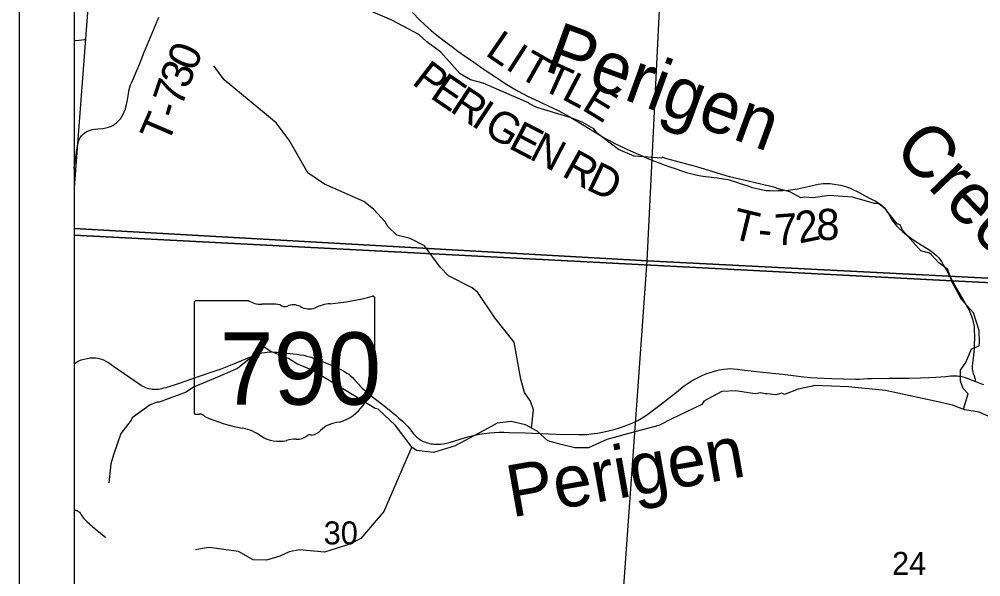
# Model space of a CAD drawing. Extents: x 0 to 34, y 0 to 22.
# Drawn here: x 2 to 3.753, y 18.895 to 19.912 of the extents above; entities that cross this region are included whole.
import ezdxf

# ---------------------------------------------------------------- set-up
doc = ezdxf.new("R2010")
doc.units = 0
for name, color, linetype in [('Default', 7, 'Continuous'), ('GM_X_Minor_River', 7, 'Continuous'), ('GM_X_Minor_River_Text', 7, 'Continuous'), ('GM_X_Section', 7, 'Continuous'), ('GM_X_Section_Text', 7, 'Continuous'), ('GM_X_State_Location', 7, 'Continuous'), ('GM_X_State_Route', 7, 'Continuous'), ('GM_X_State_Shield', 7, 'Continuous'), ('GM_X_Township_Road', 7, 'Continuous'), ('GM_X_Township_Road_Text', 7, 'Continuous'), ('SH_Cut_Line', 7, 'Continuous'), ('SH_Data', 7, 'Continuous')]:
    doc.layers.add(name, color=color, linetype=linetype)

msp = doc.modelspace()

# ---------------------------------------------------------------- linework, layer by layer
at = {"layer": 'Default'}
msp.add_lwpolyline([(6.3694, 20.9), (2.1, 20.9), (2.1, 19.5179), (3.7007, 19.4348), (4.4284, 19.3984), (4.7013, 19.3856), (5.4875, 19.3459)], dxfattribs=at)
for points in [[(2.1, 19.605), (2.1, 19.53), (3.1447, 19.4715), (3.1945, 20.4863), (2.1714, 20.5391)], [(2.1, 19.53), (2.1, 18.4931), (3.0707, 18.4461), (3.1447, 19.4715)], [(2.1, 19.5179), (2.1, 14.1), (5.687, 14.1), (5.785, 14.1504), (5.9145, 14.1963), (5.9273, 14.1959), (5.9341, 14.3014), (6.0001, 15.328), (6.0418, 15.9539), (6.0633, 16.2368), (6.0901, 16.6706), (6.1151, 17.0743), (6.1723, 18.0255), (6.1917, 18.3385), (6.2282, 18.9116), (6.2536, 19.3066), (5.4875, 19.3459), (4.7013, 19.3856), (4.4284, 19.3984), (3.7007, 19.4348)]]:
    msp.add_lwpolyline(points, close=True, dxfattribs=at)
at = {"layer": 'GM_X_Minor_River'}
for points in [[(3.7208, 19.2007), (3.7294, 19.2286), (3.7207, 19.2388), (3.7154, 19.2517), (3.7158, 19.2719), (3.7256, 19.286), (3.7358, 19.3111), (3.7497, 19.3161), (3.7501, 19.3225), (3.7497, 19.3446), (3.7391, 19.3765), (3.7172, 19.4011), (3.6997, 19.4334), (3.6925, 19.4554), (3.6763, 19.4675), (3.663, 19.4823), (3.6592, 19.4854), (3.6433, 19.4895), (3.6097, 19.527), (3.6055, 19.5369), (3.6002, 19.5388), (3.579, 19.5654), (3.5661, 19.5756), (3.5586, 19.576), (3.5189, 19.5873), (3.5011, 19.5884), (3.4765, 19.5906), (3.4471, 19.5863), (3.4316, 19.5874), (3.4248, 19.5859), (3.4043, 19.5969), (3.3813, 19.6033), (3.3775, 19.6052), (3.2947, 19.6247), (3.2353, 19.6428), (3.1801, 19.6571), (3.1718, 19.6605), (3.171, 19.6582), (3.1208, 19.6623), (3.092, 19.6744), (3.0538, 19.7032), (3.047, 19.7119), (3.0262, 19.7244), (3.0058, 19.7323), (2.9434, 19.7508), (2.9298, 19.7576), (2.9283, 19.7595), (2.8746, 19.7822), (2.8454, 19.7954), (2.8227, 19.8015), (2.8035, 19.8121), (2.7683, 19.8519), (2.7429, 19.8704), (2.7285, 19.8841), (2.6794, 19.9102), (2.6453, 19.9249)], [(2.1, 19.8731), (2.1094, 19.8735), (2.1196, 19.875), (2.1188, 19.8746)], [(2.9338, 19.1664), (2.9372, 19.1995), (2.9317, 19.2157), (2.9212, 19.2312), (2.9144, 19.2557), (2.9021, 19.3233), (2.8671, 19.3677), (2.8356, 19.4135), (2.8253, 19.4218), (2.7821, 19.4437), (2.7675, 19.4598), (2.7388, 19.4986), (2.7127, 19.512), (2.688, 19.5181), (2.6718, 19.5338), (2.6668, 19.5427), (2.6459, 19.5658), (2.6282, 19.5796), (2.5566, 19.6112), (2.5262, 19.6315), (2.4921, 19.6914), (2.4685, 19.7226), (2.3734, 19.8012), (2.3581, 19.8218), (2.3549, 19.8268)], [(3.4494, 19.2443), (3.4459, 19.2427), (3.4198, 19.2373), (3.3949, 19.2278), (3.39, 19.23), (3.379, 19.2273), (3.3635, 19.2288), (3.3597, 19.2288), (3.3514, 19.2307), (3.3416, 19.2288), (3.3057, 19.2344), (3.2807, 19.2332), (3.2475, 19.2156), (3.2441, 19.2095), (3.1893, 19.1835), (3.1658, 19.1713), (3.122, 19.1594), (3.071, 19.1456), (3.0374, 19.1303), (3.034, 19.1303), (3.0128, 19.1303), (2.9878, 19.1367), (2.9636, 19.1434), (2.9443, 19.1605), (2.9228, 19.1722), (2.8967, 19.1782), (2.871, 19.1755), (2.8544, 19.166), (2.7943, 19.1339), (2.755, 19.122), (2.724, 19.1257), (2.7164, 19.131), (2.6861, 19.1709), (2.6544, 19.2012), (2.6487, 19.2023), (2.5678, 19.2515), (2.533, 19.2727), (2.5061, 19.2833), (2.4906, 19.2932), (2.4573, 19.3068), (2.4441, 19.3159), (2.4399, 19.3178), (2.4305, 19.3014), (2.4139, 19.2877), (2.398, 19.2751), (2.3572, 19.2575), (2.3179, 19.2411), (2.3043, 19.2319), (2.2552, 19.2139), (2.2514, 19.2135), (2.2385, 19.2089), (2.2061, 19.1853), (2.2042, 19.1807), (2.1849, 19.1567), (2.1717, 19.1175), (2.1668, 19.1012), (2.1631, 19.0666)], [(3.7729, 19.185), (3.7499, 19.1952), (3.7234, 19.1997), (3.7011, 19.2084), (3.6686, 19.2155), (3.579, 19.2347), (3.5113, 19.2417), (3.4494, 19.2443)], [(2.7156, 19.1322), (2.699, 19.0947), (2.6648, 19.0145), (2.6229, 18.9654), (2.6025, 18.9546), (2.5563, 18.9405), (2.5107, 18.9442), (2.4917, 18.9407), (2.4748, 18.9332), (2.4504, 18.9257), (2.4266, 18.9264), (2.3999, 18.9413), (2.346, 18.9487), (2.3343, 18.9468), (2.321, 18.9446)]]:
    msp.add_lwpolyline(points, dxfattribs=at)
at = {"layer": 'GM_X_Section'}
for points in [[(3.1945, 20.4863), (4.2301, 20.4313), (4.1716, 19.4188), (3.1447, 19.4715)], [(3.1447, 19.4715), (4.1716, 19.4188), (4.1036, 18.4009), (3.0707, 18.4461)]]:
    msp.add_lwpolyline(points, close=True, dxfattribs=at)
at = {"layer": 'GM_X_State_Route'}
msp.add_lwpolyline([(2.1, 19.2838), (2.1023, 19.2853), (2.1075, 19.2882), (2.113, 19.2906), (2.1181, 19.2922), (2.1239, 19.2935), (2.129, 19.2943), (2.134, 19.2945), (2.1389, 19.2943), (2.1435, 19.2938), (2.1483, 19.2927), (2.151, 19.2917), (2.1538, 19.2906), (2.1581, 19.2882), (2.1631, 19.2852), (2.1673, 19.2824), (2.1721, 19.2791), (2.2184, 19.2469), (2.2226, 19.2443), (2.2266, 19.242), (2.2304, 19.2404), (2.2333, 19.2392), (2.2365, 19.2383), (2.2398, 19.2377), (2.2427, 19.2373), (2.2457, 19.2372), (2.2488, 19.2372), (2.2512, 19.2374), (2.2536, 19.2376), (2.2569, 19.2381), (2.26, 19.2386), (2.2638, 19.2395), (2.2679, 19.2405), (2.2901, 19.2479), (2.3251, 19.2597), (2.3573, 19.2707), (2.3697, 19.2752), (2.3853, 19.2811), (2.4266, 19.2983), (2.4321, 19.3005), (2.4373, 19.3022), (2.4429, 19.3036), (2.4476, 19.3045), (2.4521, 19.305), (2.4565, 19.3052), (2.4608, 19.3053), (2.4653, 19.3051), (2.4702, 19.3048), (2.5052, 19.3011), (2.512, 19.3002), (2.5185, 19.2991), (2.5241, 19.2977), (2.5297, 19.2961), (2.545, 19.2909), (2.5571, 19.2861), (2.5703, 19.2805), (2.5793, 19.2764), (2.5871, 19.2726), (2.593, 19.2694), (2.5973, 19.2668), (2.6007, 19.2644), (2.6039, 19.2618), (2.6072, 19.2588), (2.6119, 19.2539), (2.6186, 19.2463), (2.6215, 19.2429), (2.6249, 19.2393), (2.6285, 19.236), (2.6326, 19.2324), (2.6368, 19.2291), (2.6414, 19.2255), (2.6621, 19.2095), (2.6776, 19.1971), (2.6815, 19.1939), (2.6862, 19.19), (2.6909, 19.186), (2.695, 19.1823), (2.6987, 19.1789), (2.7022, 19.1754), (2.7057, 19.1719), (2.7087, 19.1685), (2.7114, 19.1654), (2.7157, 19.1601), (2.7183, 19.1568), (2.7213, 19.1534), (2.724, 19.1506), (2.7269, 19.1479), (2.7295, 19.146), (2.7322, 19.1443), (2.7365, 19.1422), (2.7391, 19.1411), (2.7416, 19.1402), (2.7445, 19.1393), (2.7475, 19.1386), (2.7503, 19.1379), (2.7532, 19.1375), (2.7557, 19.1371), (2.7584, 19.137), (2.7609, 19.1369), (2.7634, 19.1369), (2.7679, 19.1371), (2.7726, 19.1375), (2.7769, 19.1383), (2.7815, 19.1393), (2.7921, 19.1424), (2.8056, 19.1467), (2.8174, 19.1502), (2.8296, 19.1533), (2.8386, 19.1552), (2.8477, 19.1567), (2.857, 19.1578), (2.8658, 19.1584), (2.8741, 19.1587), (2.8832, 19.1588), (2.8931, 19.1584), (2.9223, 19.1575), (2.9784, 19.1556), (3.0202, 19.1545), (3.0273, 19.1547), (3.034, 19.155), (3.0433, 19.1557), (3.0538, 19.1571), (3.063, 19.1588), (3.074, 19.1613), (3.0842, 19.164), (3.0961, 19.1676), (3.1091, 19.1721), (3.1183, 19.176), (3.1262, 19.1798), (3.1338, 19.1841), (3.1432, 19.1902), (3.1529, 19.197), (3.1654, 19.2063), (3.1977, 19.232), (3.2053, 19.2381), (3.2103, 19.242), (3.2153, 19.2458), (3.2212, 19.2497), (3.2276, 19.2535), (3.2352, 19.2576), (3.2435, 19.2617), (3.2515, 19.2651), (3.2596, 19.268), (3.2673, 19.2704), (3.2757, 19.2725), (3.2842, 19.274), (3.2909, 19.2747), (3.2952, 19.2748), (3.3013, 19.2747), (3.3093, 19.274), (3.3222, 19.2722), (3.3339, 19.2706), (3.344, 19.2693), (3.3552, 19.2681), (3.3909, 19.2649), (3.4302, 19.2598), (3.4419, 19.2587), (3.4541, 19.2581), (3.4805, 19.2571), (3.5242, 19.2558), (3.5314, 19.2558), (3.5458, 19.2565), (3.5502, 19.2568), (3.5543, 19.257), (3.5857, 19.2575), (3.6216, 19.2576), (3.6428, 19.2578), (3.6579, 19.2584), (3.6704, 19.2591), (3.6886, 19.2606), (3.6976, 19.2616), (3.7025, 19.2619), (3.7062, 19.2618), (3.7095, 19.2616), (3.7128, 19.2613), (3.7157, 19.2609), (3.7197, 19.2599), (3.724, 19.2585), (3.7289, 19.2568), (3.743, 19.2512), (3.7518, 19.2477), (3.7574, 19.2457)], dxfattribs=at)
at = {"layer": 'GM_X_State_Shield'}
for p, q in [((2.6482, 19.2988), (2.6482, 19.4035)), ((2.3186, 19.3951), (2.3186, 19.1949)), ((2.4184, 19.3985), (2.3219, 19.3985)), ((2.6482, 19.2988), (2.6482, 19.2988))]:
    msp.add_line(p, q, dxfattribs=at)
for centre, major_axis, start_param, end_param in [((2.5308, 19.6713), (0.3495, 0), 4.814394, 5.042369), ((2.6445, 19.4039), (0.00367, 0), 6.141152, 7.989035), ((2.3224, 19.3955), (0.00382, 0), 1.712693, 3.28349), ((2.4414, 19.4217), (0.037, 0), 4.042523, 4.731795), ((2.4536, 19.2862), (0.133, 0), 1.404758, 1.657858), ((2.4838, 19.3965), (0.0107, 0), 3.836095, 5.185415), ((2.4995, 19.3734), (0.0222, 0), 0.950623, 2.079405), ((2.5282, 19.4051), (0.0267, 0), 4.081561, 5.145723), ((2.5754, 19.3374), (0.0703, 0), 1.699011, 2.107814), ((2.6474, 19.2911), (0.00568, 0), 1.883978, 3.671073), ((2.6443, 19.2984), (0.00393, 0), 5.05454, 6.418171), ((2.6112, 19.2779), (0.0341, 0), 5.934695, 6.695948), ((2.6613, 19.255), (0.0248, 0), 2.387724, 3.262537), ((2.5504, 19.2417), (0.0874, 0), 5.101752, 6.440018), ((2.3224, 19.1945), (0.00385, 0), 3.00124, 4.508301), ((2.323, 19.215), (0.0294, 0), 4.665946, 4.897461), ((2.329, 19.1834), (0.0106, 0), 0.519207, 1.627899), ((2.4629, 19.3632), (0.2524, 0), 4.195997, 4.488961), ((2.5872, 19.1388), (0.0479, 0), 1.647645, 2.488434), ((2.3876, 19.105), (0.079, 0), 0.823519, 1.323587), ((2.5266, 19.1755), (0.0282, 0), 4.937069, 5.64225), ((2.473, 19.1824), (0.0501, 0), 4.026481, 4.996735), ((2.502, 19.1132), (0.0412, 0), 1.495662, 1.94098), ((2.5056, 19.1674), (0.0267, 0), 4.691044, 5.507374), ((2.5298, 19.148), (0.00752, 0), 1.147584, 2.315152)]:
    msp.add_ellipse(centre, major_axis=major_axis, ratio=0.8, start_param=start_param, end_param=end_param, dxfattribs=at)
at = {"layer": 'GM_X_Township_Road'}
for points in [[(2.1, 19.6399), (2.1008, 19.6452), (2.1037, 19.6648), (2.1056, 19.6773), (2.1069, 19.6845), (2.108, 19.6888), (2.1094, 19.6926), (2.1112, 19.6959), (2.1135, 19.6991), (2.1164, 19.7022), (2.1198, 19.7049), (2.1228, 19.7069), (2.1262, 19.7086), (2.1293, 19.7098), (2.1333, 19.711), (2.1374, 19.7116), (2.1435, 19.7122), (2.1522, 19.7128), (2.1578, 19.7136), (2.1627, 19.7148), (2.1668, 19.7163), (2.1708, 19.7182), (2.1739, 19.7202), (2.1774, 19.7229), (2.1811, 19.7264), (2.1843, 19.7302), (2.1872, 19.7343), (2.1897, 19.7387), (2.1915, 19.7427), (2.1934, 19.748), (2.1946, 19.7521), (2.1957, 19.7566), (2.1966, 19.7611), (2.1989, 19.776), (2.2002, 19.7839), (2.2013, 19.7882), (2.2028, 19.7923), (2.2045, 19.7961), (2.2082, 19.8039), (2.2128, 19.8142), (2.2197, 19.8311), (2.228, 19.8517), (2.2334, 19.8642), (2.2423, 19.8862), (2.2543, 19.9157)], [(2.7166, 19.9238), (2.731, 19.9095), (2.7381, 19.9027), (2.7452, 19.8963), (2.7517, 19.8905), (2.7578, 19.8853), (2.7665, 19.8785), (2.7768, 19.8707), (2.7879, 19.8624), (2.7996, 19.8537), (2.8114, 19.8449), (2.8285, 19.8332), (2.8477, 19.82), (2.8666, 19.8074), (2.8775, 19.8), (2.8857, 19.7947), (2.8945, 19.7892), (2.9054, 19.7828), (2.9162, 19.7768), (2.929, 19.7703), (2.9385, 19.7658), (2.9643, 19.754), (2.9823, 19.7454), (2.9982, 19.7369), (3.0156, 19.7267), (3.0329, 19.7163), (3.0503, 19.7052), (3.0594, 19.6998), (3.0674, 19.6952), (3.0756, 19.6906), (3.0857, 19.6853), (3.0959, 19.6802), (3.1075, 19.6747), (3.1197, 19.6692), (3.1324, 19.6637), (3.146, 19.6581), (3.1563, 19.6537), (3.1666, 19.6497), (3.1754, 19.6465), (3.1859, 19.6428), (3.1955, 19.6395), (3.2053, 19.6361), (3.2159, 19.6326), (3.2237, 19.6304), (3.2334, 19.6282), (3.2425, 19.6265), (3.2511, 19.6252), (3.2615, 19.6239), (3.2719, 19.6226), (3.2834, 19.6209), (3.2876, 19.6202), (3.2917, 19.6193), (3.2957, 19.6183), (3.2996, 19.6173), (3.3054, 19.6155), (3.3142, 19.6125), (3.3259, 19.6084), (3.336, 19.6053), (3.3416, 19.6038), (3.3468, 19.6025), (3.3553, 19.6007), (3.3615, 19.5998), (3.3684, 19.5994), (3.375, 19.5992), (3.3829, 19.5994), (3.3924, 19.5998), (3.4009, 19.6004), (3.4102, 19.6013), (3.4188, 19.6027), (3.4292, 19.605), (3.4403, 19.6075), (3.4561, 19.6108), (3.4611, 19.6115), (3.465, 19.612), (3.4695, 19.6123), (3.4733, 19.6123), (3.4774, 19.6122), (3.4814, 19.6118), (3.4852, 19.6113), (3.4934, 19.6099), (3.4977, 19.609), (3.502, 19.6079), (3.5057, 19.6068), (3.5097, 19.6056), (3.5134, 19.6042), (3.5171, 19.6026), (3.5294, 19.5966), (3.5409, 19.5905), (3.5536, 19.584), (3.5612, 19.5798), (3.5665, 19.5764), (3.5707, 19.5735), (3.5736, 19.5711), (3.5766, 19.5683), (3.5793, 19.565), (3.5822, 19.5609), (3.5847, 19.5566), (3.5868, 19.5528), (3.5899, 19.5475), (3.593, 19.5428), (3.596, 19.5389), (3.5992, 19.5352), (3.6041, 19.5302), (3.6101, 19.5248), (3.6144, 19.5212), (3.6187, 19.5177), (3.6247, 19.5132), (3.6289, 19.5103), (3.6334, 19.5072), (3.6407, 19.5026), (3.6576, 19.4922), (3.6622, 19.4891), (3.6671, 19.4853), (3.6718, 19.4812), (3.6752, 19.4776), (3.678, 19.4742), (3.6808, 19.4701), (3.6843, 19.4642), (3.6906, 19.4529), (3.6939, 19.4469), (3.6971, 19.441), (3.7009, 19.4343)], [(3.7009, 19.4343), (3.7085, 19.4209), (3.7218, 19.3979), (3.7286, 19.3865), (3.7314, 19.3812), (3.7338, 19.3756), (3.7358, 19.3702), (3.7375, 19.3649), (3.7389, 19.3596), (3.7397, 19.3551), (3.7403, 19.3504), (3.7407, 19.3433), (3.7409, 19.3357), (3.741, 19.3318), (3.741, 19.3274), (3.7408, 19.3221), (3.7406, 19.3166), (3.7402, 19.3107), (3.7396, 19.3049), (3.739, 19.2993), (3.7384, 19.2938), (3.7374, 19.2847), (3.7369, 19.2789), (3.7368, 19.2765), (3.737, 19.274), (3.7373, 19.2716), (3.738, 19.2686), (3.7388, 19.2662), (3.7405, 19.2616), (3.7418, 19.2575), (3.7424, 19.2553), (3.7426, 19.2539), (3.743, 19.2512)], [(2.1, 19.0168), (2.1016, 19.0169), (2.1032, 19.0168), (2.1047, 19.0164), (2.1065, 19.0156), (2.1082, 19.0144), (2.1096, 19.0131), (2.1109, 19.0116), (2.112, 19.0101), (2.1131, 19.0083), (2.1173, 19.0023), (2.1187, 19.0006), (2.1203, 18.999), (2.1232, 18.9963), (2.1384, 18.983), (2.158, 18.9667)]]:
    msp.add_lwpolyline(points, dxfattribs=at)
at = {"layer": 'SH_Cut_Line'}
msp.add_lwpolyline([(8.9, 14.1), (8.9, 20.9), (2.1, 20.9), (2.1, 14.1)], dxfattribs=at)
at = {"layer": 'SH_Data'}
for p, q in [((2, 21), (2, 14)), ((2.1, 20.9), (2.1, 14.1))]:
    msp.add_line(p, q, dxfattribs=at)

# ---------------------------------------------------------------- texts
at = {"layer": 'GM_X_Minor_River_Text'}
for s, height, rotation, p in [('Perigen', 0.09469, 340.0029, (2.954, 19.8193)), ('Creek', 0.0947, 314.0019, (3.5904, 19.6715)), ('Perigen', 0.0947, 10.0083, (2.8975, 19.0033))]:
    msp.add_text(s, height=height, rotation=rotation, dxfattribs=at).set_placement(p)
at = {"layer": 'GM_X_Section_Text'}
for s, p in [('30', (2.5549, 18.9544)), ('24', (3.5908, 18.8988))]:
    msp.add_text(s, height=0.04186, rotation=0, dxfattribs=at).set_placement(p)
at = {"layer": 'GM_X_State_Location'}
for s in ['s', 'r']:
    msp.add_text(s, height=0.000189, dxfattribs=at).set_placement((2.4797, 19.2817))
msp.add_text('790', height=0.000189, rotation=0, dxfattribs=at).set_placement((2.4128, 19.2679))
at = {"layer": 'GM_X_State_Shield'}
msp.add_text('790', height=0.13184, dxfattribs=at).set_placement((2.3656, 19.2091))
at = {"layer": 'GM_X_Township_Road_Text'}
for s, rotation, p in [('L', 325.4107, (2.8473, 19.8476)), ('0', 67.5356, (2.3199, 19.8149)), ('I', 327.159, (2.8839, 19.8224)), ('T', 330.5158, (2.9065, 19.8079)), ('3', 68.5958, (2.3072, 19.7826)), ('P', 322.463, (2.7135, 19.795)), ('T', 335.7988, (2.9485, 19.7845)), ('7', 71.2343, (2.2962, 19.7501)), ('E', 325.5485, (2.7466, 19.7697)), ('L', 332.1047, (2.9864, 19.7675)), ('R', 326.635, (2.7826, 19.745)), ('E', 328.4839, (3.0232, 19.7481)), ('-', 73.8409, (2.2899, 19.7284)), ('I', 326.7269, (2.8217, 19.7193)), ('T', 66.7015, (2.2705, 19.6821)), ('G', 329.3578, (2.8436, 19.705)), ('E', 332.4783, (2.8896, 19.6779)), ('N', 332.4428, (2.9273, 19.6582)), ('R', 330.8612, (2.9867, 19.6271)), ('D', 334.4086, (3.0309, 19.6026)), ('T', 346.3411, (3.2951, 19.5131)), ('7', 3.9594, (3.3785, 19.4991)), ('2', 11.512, (3.4215, 19.5027)), ('8', 359.9349, (3.4528, 19.5093)), ('-', 354.1829, (3.3447, 19.5017))]:
    msp.add_text(s, height=0.0568, rotation=rotation, dxfattribs=at).set_placement(p)

doc.saveas('drawing.dxf')
